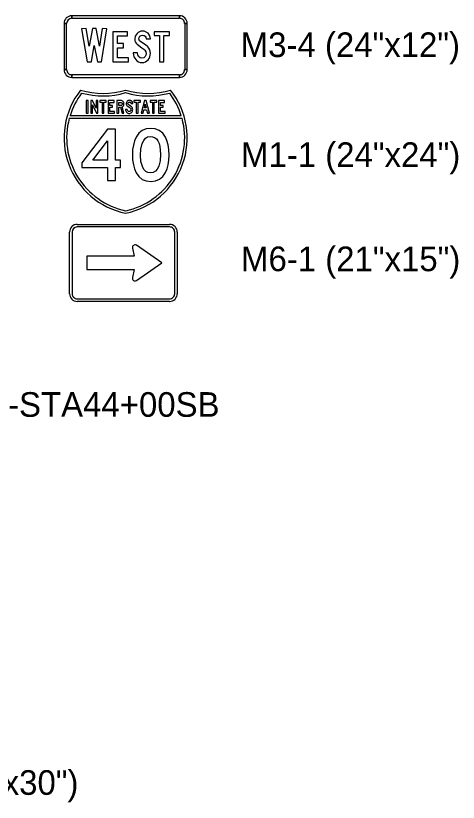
# Model space of a CAD drawing. Extents: x 620856.8 to 620948.6, y 415598.8 to 415658.2.
# Drawn here: x 620920.43 to 620927.61, y 415628.02 to 415640.79 of the extents above; entities that cross this region are included whole.
import ezdxf

# ---------------------------------------------------------------- set-up
doc = ezdxf.new("R2010")
doc.units = 0
doc.layers.add('SIGNS', color=7, linetype='Continuous')

msp = doc.modelspace()

# ---------------------------------------------------------------- linework, layer by layer
at = {"layer": 'SIGNS'}
for p, q in [((620921.335, 415640.745), (620921.335, 415640.787)), ((620923.085, 415640.787), (620923.085, 415640.745)), ((620921.21, 415640.662), (620921.252, 415640.662)), ((620923.169, 415640.662), (620923.21, 415640.662)), ((620921.252, 415639.912), (620921.21, 415639.912)), ((620921.335, 415639.787), (620921.335, 415639.829)), ((620923.085, 415639.829), (620923.085, 415639.787)), ((620923.21, 415639.912), (620923.169, 415639.912)), ((620921.599, 415639.41), (620921.57, 415639.41)), ((620921.57, 415639.41), (620921.57, 415639.205)), ((620921.599, 415639.205), (620921.599, 415639.41)), ((620921.673, 415639.41), (620921.645, 415639.41)), ((620921.645, 415639.41), (620921.645, 415639.205)), ((620921.729, 415639.288), (620921.673, 415639.41)), ((620921.673, 415639.205), (620921.673, 415639.343)), ((620921.673, 415639.343), (620921.737, 415639.205)), ((620921.76, 415639.41), (620921.729, 415639.41)), ((620921.729, 415639.41), (620921.729, 415639.288)), ((620921.76, 415639.205), (620921.76, 415639.41)), ((620921.896, 415639.41), (620921.791, 415639.41)), ((620921.791, 415639.41), (620921.791, 415639.384)), ((620921.791, 415639.384), (620921.828, 415639.384)), ((620921.828, 415639.384), (620921.828, 415639.205)), ((620921.857, 415639.205), (620921.857, 415639.384)), ((620921.857, 415639.384), (620921.896, 415639.384)), ((620921.896, 415639.384), (620921.896, 415639.41)), ((620922.023, 415639.41), (620921.926, 415639.41)), ((620921.926, 415639.41), (620921.926, 415639.205)), ((620921.956, 415639.329), (620921.956, 415639.381)), ((620921.956, 415639.381), (620922.023, 415639.381)), ((620921.998, 415639.329), (620921.956, 415639.329)), ((620921.998, 415639.301), (620921.998, 415639.329)), ((620922.023, 415639.381), (620922.023, 415639.41)), ((620922.222, 415639.381), (620922.219, 415639.361)), ((620922.219, 415639.361), (620922.219, 415639.35)), ((620922.219, 415639.35), (620922.222, 415639.341)), ((620922.234, 415639.398), (620922.222, 415639.381)), ((620922.222, 415639.341), (620922.227, 415639.332)), ((620922.227, 415639.332), (620922.234, 415639.324)), ((620922.242, 415639.405), (620922.234, 415639.398)), ((620922.234, 415639.324), (620922.267, 415639.301)), ((620922.251, 415639.41), (620922.242, 415639.405)), ((620922.247, 415639.362), (620922.249, 415639.371)), ((620922.248, 415639.355), (620922.247, 415639.362)), ((620922.251, 415639.349), (620922.248, 415639.355)), ((620922.249, 415639.371), (620922.254, 415639.378)), ((620922.26, 415639.413), (620922.251, 415639.41)), ((620922.267, 415639.337), (620922.251, 415639.349)), ((620922.254, 415639.378), (620922.262, 415639.384)), ((620922.271, 415639.414), (620922.26, 415639.413)), ((620922.262, 415639.384), (620922.272, 415639.385)), ((620922.291, 415639.321), (620922.267, 415639.337)), ((620922.282, 415639.413), (620922.271, 415639.414)), ((620922.272, 415639.385), (620922.282, 415639.384)), ((620922.292, 415639.41), (620922.282, 415639.413)), ((620922.282, 415639.384), (620922.289, 415639.379)), ((620922.289, 415639.379), (620922.293, 415639.372)), ((620922.306, 415639.307), (620922.291, 415639.321)), ((620922.301, 415639.405), (620922.292, 415639.41)), ((620922.293, 415639.372), (620922.296, 415639.362)), ((620922.296, 415639.362), (620922.325, 415639.362)), ((620922.309, 415639.399), (620922.301, 415639.405)), ((620922.32, 415639.382), (620922.309, 415639.399)), ((620922.325, 415639.362), (620922.32, 415639.382)), ((620922.45, 415639.41), (620922.345, 415639.41)), ((620922.345, 415639.41), (620922.345, 415639.384)), ((620922.345, 415639.384), (620922.382, 415639.384)), ((620922.382, 415639.384), (620922.382, 415639.205)), ((620922.412, 415639.205), (620922.412, 415639.384)), ((620922.412, 415639.384), (620922.45, 415639.384)), ((620922.45, 415639.384), (620922.45, 415639.41)), ((620922.714, 415639.41), (620922.609, 415639.41)), ((620922.609, 415639.41), (620922.609, 415639.384)), ((620922.609, 415639.384), (620922.647, 415639.384)), ((620922.647, 415639.384), (620922.647, 415639.205)), ((620922.676, 415639.205), (620922.676, 415639.384)), ((620922.676, 415639.384), (620922.714, 415639.384)), ((620922.714, 415639.384), (620922.714, 415639.41)), ((620922.842, 415639.41), (620922.745, 415639.41)), ((620922.745, 415639.41), (620922.745, 415639.205)), ((620922.775, 415639.329), (620922.775, 415639.381)), ((620922.775, 415639.381), (620922.842, 415639.381)), ((620922.817, 415639.329), (620922.775, 415639.329)), ((620922.817, 415639.301), (620922.817, 415639.329)), ((620922.842, 415639.381), (620922.842, 415639.41)), ((620921.57, 415639.205), (620921.599, 415639.205)), ((620921.645, 415639.205), (620921.673, 415639.205)), ((620921.737, 415639.205), (620921.76, 415639.205)), ((620921.828, 415639.205), (620921.857, 415639.205)), ((620921.926, 415639.205), (620922.031, 415639.205)), ((620921.956, 415639.233), (620921.956, 415639.301)), ((620921.956, 415639.301), (620921.998, 415639.301)), ((620922.031, 415639.233), (620921.956, 415639.233)), ((620922.031, 415639.205), (620922.031, 415639.233)), ((620922.237, 415639.267), (620922.209, 415639.267)), ((620922.209, 415639.267), (620922.209, 415639.265)), ((620922.209, 415639.265), (620922.21, 415639.252)), ((620922.21, 415639.252), (620922.213, 415639.241)), ((620922.213, 415639.241), (620922.218, 415639.23)), ((620922.218, 415639.23), (620922.225, 415639.221)), ((620922.225, 415639.221), (620922.234, 415639.212)), ((620922.234, 415639.212), (620922.244, 415639.206)), ((620922.239, 415639.253), (620922.237, 415639.267)), ((620922.245, 415639.242), (620922.239, 415639.253)), ((620922.244, 415639.206), (620922.255, 415639.202)), ((620922.255, 415639.234), (620922.245, 415639.242)), ((620922.267, 415639.231), (620922.255, 415639.234)), ((620922.255, 415639.202), (620922.267, 415639.201)), ((620922.267, 415639.301), (620922.28, 415639.291)), ((620922.279, 415639.233), (620922.267, 415639.231)), ((620922.267, 415639.201), (620922.279, 415639.202)), ((620922.289, 415639.241), (620922.279, 415639.233)), ((620922.279, 415639.202), (620922.29, 415639.206)), ((620922.28, 415639.291), (620922.287, 415639.284)), ((620922.287, 415639.284), (620922.294, 415639.274)), ((620922.294, 415639.251), (620922.289, 415639.241)), ((620922.29, 415639.206), (620922.3, 415639.212)), ((620922.294, 415639.274), (620922.296, 415639.263)), ((620922.296, 415639.263), (620922.294, 415639.251)), ((620922.3, 415639.212), (620922.309, 415639.22)), ((620922.314, 415639.297), (620922.306, 415639.307)), ((620922.309, 415639.22), (620922.316, 415639.229)), ((620922.32, 415639.287), (620922.314, 415639.297)), ((620922.316, 415639.229), (620922.321, 415639.24)), ((620922.323, 415639.275), (620922.32, 415639.287)), ((620922.321, 415639.24), (620922.324, 415639.251)), ((620922.325, 415639.264), (620922.323, 415639.275)), ((620922.324, 415639.251), (620922.325, 415639.264)), ((620922.382, 415639.205), (620922.412, 415639.205)), ((620922.647, 415639.205), (620922.676, 415639.205)), ((620922.745, 415639.205), (620922.85, 415639.205)), ((620922.775, 415639.233), (620922.775, 415639.301)), ((620922.775, 415639.301), (620922.817, 415639.301)), ((620922.85, 415639.233), (620922.775, 415639.233)), ((620922.85, 415639.205), (620922.85, 415639.233)), ((620923.114, 415639.164), (620921.306, 415639.164)), ((620921.424, 415637.4), (620922.924, 415637.4)), ((620922.924, 415637.4), (620922.924, 415637.4)), ((620921.299, 415636.275), (620921.299, 415637.275)), ((620921.341, 415637.275), (620921.341, 415636.275)), ((620922.924, 415637.359), (620921.424, 415637.359)), ((620923.008, 415636.275), (620923.008, 415637.275)), ((620923.049, 415637.275), (620923.049, 415636.275)), ((620922.799, 415636.775), (620922.384, 415637.061)), ((620922.321, 415637.016), (620922.351, 415636.885)), ((620922.351, 415636.885), (620921.58, 415636.885)), ((620921.58, 415636.885), (620921.58, 415636.666)), ((620922.384, 415636.49), (620922.799, 415636.775)), ((620921.58, 415636.666), (620922.351, 415636.666)), ((620922.351, 415636.666), (620922.321, 415636.535)), ((620921.424, 415636.192), (620922.924, 415636.192)), ((620922.924, 415636.15), (620921.424, 415636.15)), ((620921.424, 415636.15), (620921.424, 415636.15))]:
    msp.add_line(p, q, dxfattribs=at)
for points in [[(620923.085, 415640.787), (620921.335, 415640.787), (620921.335, 415640.745), (620923.085, 415640.745), (620923.085, 415640.787), (620923.085, 415640.787)], [(620921.21, 415640.662), (620921.21, 415639.912), (620921.252, 415639.912), (620921.252, 415640.662), (620921.21, 415640.662), (620921.21, 415640.662)], [(620923.21, 415639.912), (620923.21, 415640.662), (620923.169, 415640.662), (620923.169, 415639.912), (620923.21, 415639.912), (620923.21, 415639.912)], [(620921.583, 415640.037), (620921.655, 415640.037), (620921.699, 415640.306), (620921.752, 415640.037), (620921.819, 415640.037), (620921.907, 415640.576), (620921.831, 415640.581), (620921.783, 415640.291), (620921.73, 415640.581), (620921.67, 415640.581), (620921.616, 415640.291), (620921.57, 415640.581), (620921.493, 415640.576)], [(620922.257, 415640.104), (620922.076, 415640.104), (620922.076, 415640.268), (620922.178, 415640.268), (620922.178, 415640.335), (620922.076, 415640.335), (620922.076, 415640.46), (620922.238, 415640.46), (620922.238, 415640.527), (620922.004, 415640.527), (620922.004, 415640.037), (620922.257, 415640.037)], [(620922.335, 415640.184), (620922.335, 415640.18), (620922.337, 415640.15), (620922.345, 415640.122), (620922.357, 415640.097), (620922.373, 415640.074), (620922.394, 415640.053), (620922.419, 415640.039), (620922.445, 415640.03), (620922.474, 415640.027), (620922.503, 415640.03), (620922.53, 415640.039), (620922.554, 415640.053), (620922.575, 415640.072), (620922.591, 415640.095), (620922.603, 415640.12), (620922.61, 415640.147), (620922.612, 415640.177), (620922.609, 415640.206), (620922.601, 415640.233), (620922.587, 415640.258), (620922.568, 415640.282), (620922.531, 415640.314), (620922.474, 415640.353), (620922.437, 415640.382), (620922.428, 415640.396), (620922.426, 415640.412), (620922.43, 415640.434), (620922.443, 415640.453), (620922.462, 415640.465), (620922.485, 415640.469), (620922.509, 415640.465), (620922.527, 415640.454), (620922.537, 415640.437), (620922.544, 415640.412), (620922.612, 415640.412), (620922.601, 415640.462), (620922.575, 415640.502), (620922.556, 415640.517), (620922.535, 415640.528), (620922.51, 415640.535), (620922.483, 415640.537), (620922.458, 415640.535), (620922.435, 415640.528), (620922.414, 415640.516), (620922.395, 415640.499), (620922.367, 415640.458), (620922.358, 415640.41), (620922.36, 415640.386), (620922.367, 415640.363), (620922.379, 415640.342), (620922.395, 415640.323), (620922.475, 415640.266), (620922.504, 415640.244), (620922.523, 415640.227), (620922.539, 415640.203), (620922.544, 415640.176), (620922.54, 415640.147), (620922.526, 415640.123), (620922.503, 415640.105), (620922.474, 415640.099), (620922.444, 415640.105), (620922.421, 415640.126), (620922.407, 415640.152), (620922.403, 415640.184)], [(620922.762, 415640.037), (620922.833, 415640.037), (620922.833, 415640.466), (620922.925, 415640.466), (620922.925, 415640.527), (620922.672, 415640.527), (620922.672, 415640.466), (620922.762, 415640.466)], [(620921.335, 415639.787), (620923.085, 415639.787), (620923.085, 415639.829), (620921.335, 415639.829), (620921.335, 415639.787), (620921.335, 415639.787)]]:
    msp.add_lwpolyline(points, close=True, dxfattribs=at)
for points in [[(620921.48, 415639.58), (620921.48, 415639.58)], [(620922.941, 415639.58), (620922.941, 415639.58)], [(620921.495, 415639.532), (620921.495, 415639.532)], [(620922.21, 415639.539), (620922.21, 415639.539)], [(620922.925, 415639.532), (620922.925, 415639.532)], [(620922.1, 415639.205), (620922.1, 415639.302), (620922.127, 415639.302), (620922.154, 415639.205), (620922.183, 415639.205), (620922.153, 415639.306), (620922.166, 415639.313), (620922.176, 415639.324), (620922.181, 415639.337), (620922.183, 415639.352), (620922.182, 415639.365), (620922.179, 415639.376), (620922.175, 415639.385), (620922.169, 415639.394), (620922.161, 415639.401), (620922.152, 415639.406), (620922.141, 415639.409), (620922.129, 415639.41), (620922.068, 415639.41), (620922.068, 415639.205), (620922.1, 415639.205)], [(620922.1, 415639.329), (620922.1, 415639.381), (620922.13, 415639.381), (620922.14, 415639.38), (620922.149, 415639.374), (620922.154, 415639.366), (620922.156, 415639.355), (620922.154, 415639.344), (620922.149, 415639.336), (620922.142, 415639.331), (620922.131, 415639.329), (620922.1, 415639.329)], [(620922.493, 415639.205), (620922.507, 415639.261), (620922.551, 415639.261), (620922.565, 415639.205), (620922.595, 415639.205), (620922.544, 415639.41), (620922.515, 415639.41), (620922.463, 415639.205), (620922.493, 415639.205)], [(620922.514, 415639.291), (620922.529, 415639.35), (620922.544, 415639.291), (620922.514, 415639.291)], [(620921.294, 415639.122), (620921.837, 415639.122), (620922.364, 415639.122), (620923.126, 415639.122)], [(620921.915, 415638.112), (620922.048, 415638.112), (620922.048, 415638.321), (620922.127, 415638.321), (620922.127, 415638.442), (620922.048, 415638.442), (620922.048, 415638.943), (620921.915, 415638.943), (620921.499, 415638.4), (620921.499, 415638.321), (620921.915, 415638.321), (620921.915, 415638.112)], [(620922.614, 415638.959), (620922.542, 415638.95), (620922.479, 415638.923), (620922.426, 415638.879), (620922.382, 415638.817), (620922.355, 415638.756), (620922.336, 415638.688), (620922.324, 415638.613), (620922.32, 415638.531), (620922.324, 415638.446), (620922.336, 415638.369), (620922.355, 415638.299), (620922.382, 415638.238), (620922.426, 415638.176), (620922.481, 415638.131), (620922.546, 415638.105), (620922.622, 415638.096), (620922.696, 415638.105), (620922.76, 415638.132), (620922.813, 415638.177), (620922.856, 415638.24), (620922.882, 415638.299), (620922.9, 415638.367), (620922.911, 415638.443), (620922.915, 415638.526), (620922.911, 415638.613), (620922.9, 415638.69), (620922.881, 415638.759), (620922.855, 415638.818), (620922.812, 415638.88), (620922.757, 415638.924), (620922.691, 415638.95), (620922.614, 415638.959)], [(620922.776, 415638.535), (620922.769, 415638.432), (620922.747, 415638.346), (620922.724, 415638.297), (620922.694, 415638.263), (620922.658, 415638.242), (620922.617, 415638.235), (620922.573, 415638.241), (620922.537, 415638.261), (620922.506, 415638.293), (620922.482, 415638.339), (620922.458, 415638.423), (620922.451, 415638.523), (620922.458, 415638.623), (620922.48, 415638.712), (620922.503, 415638.762), (620922.532, 415638.799), (620922.566, 415638.82), (620922.607, 415638.828), (620922.646, 415638.823), (620922.681, 415638.809), (620922.71, 415638.786), (620922.734, 415638.754), (620922.752, 415638.713), (620922.766, 415638.663), (620922.773, 415638.603), (620922.776, 415638.535)], [(620921.915, 415638.442), (620921.676, 415638.442), (620921.915, 415638.756), (620921.915, 415638.442)], [(620922.21, 415637.622), (620922.21, 415637.622)], [(620922.21, 415637.58), (620922.21, 415637.58)], [(620921.424, 415637.4), (620921.424, 415637.4)], [(620921.299, 415637.275), (620921.299, 415637.275)], [(620923.049, 415636.275), (620923.049, 415636.275)], [(620922.924, 415636.15), (620922.924, 415636.15)]]:
    msp.add_lwpolyline(points, dxfattribs=at)
for centre, radius, start, end in [((620921.335, 415640.662), 0.125, 90.0002, 179.9998), ((620921.335, 415640.662), 0.0833, 90.0002, 179.9998), ((620923.085, 415640.662), 0.125, 0, 90.0002), ((620923.085, 415640.662), 0.0833, 0, 90.0002), ((620921.335, 415639.912), 0.125, 179.9998, 270.0001), ((620921.335, 415639.912), 0.0833, 179.9998, 270.0001), ((620923.085, 415639.912), 0.125, 270.0001, 0.0003), ((620923.085, 415639.912), 0.0833, 270.0001, 0.0003), ((620922.46, 415638.805), 1.25, 141.669, 258.463), ((620921.845, 415640.776), 1.25, 253.009, 286.9909), ((620921.96, 415638.805), 1.25, 281.5371, 38.3311), ((620922.576, 415640.776), 1.25, 253.0091, 286.9911), ((620922.46, 415638.804), 1.208, 142.9959, 162.6952), ((620921.842, 415640.777), 1.292, 254.4391, 286.5746), ((620922.579, 415640.777), 1.292, 253.4255, 285.561), ((620921.961, 415638.804), 1.208, 17.3047, 37.0041), ((620922.46, 415638.804), 1.208, 164.7534, 258.0704), ((620921.961, 415638.804), 1.208, 281.9296, 15.2467), ((620921.961, 415638.804), 1.208, 281.9296118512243, 281.9296385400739), ((620922.46, 415638.804), 1.208, 258.0704, 258.0705), ((620921.424, 415637.275), 0.125, 90.0002, 179.9998), ((620922.924, 415637.275), 0.125, 0, 90), ((620921.424, 415637.275), 0.0833, 90.0002, 179.9998), ((620922.924, 415637.275), 0.0833, 0, 90.0002), ((620922.362, 415637.025), 0.0417, 57.7244, 192.9504), ((620922.362, 415636.525), 0.0417, 167.0499, 302.2759), ((620921.424, 415636.275), 0.125, 179.9998, 270), ((620921.424, 415636.275), 0.0833, 179.9998, 270.0001), ((620922.924, 415636.275), 0.125, 270.0001, 360), ((620922.924, 415636.275), 0.0833, 270.0001, 0.0003)]:
    msp.add_arc(centre, radius, start, end, dxfattribs=at)

# ---------------------------------------------------------------- texts
for s, p in [('M3-4 (24"x12")', (620924.079, 415640.116)), ('M1-1 (24"x24")', (620924.084, 415638.332)), ('M6-1 (21"x15")', (620924.084, 415636.64)), ('SS-HWY59-17-STA44+00SB', (620916.793, 415634.276)), ('R5-1a (42"x30")', (620917.645, 415628.139))]:
    msp.add_text(s, height=0.4, rotation=0, dxfattribs=at).set_placement(p)

doc.saveas('drawing.dxf')
